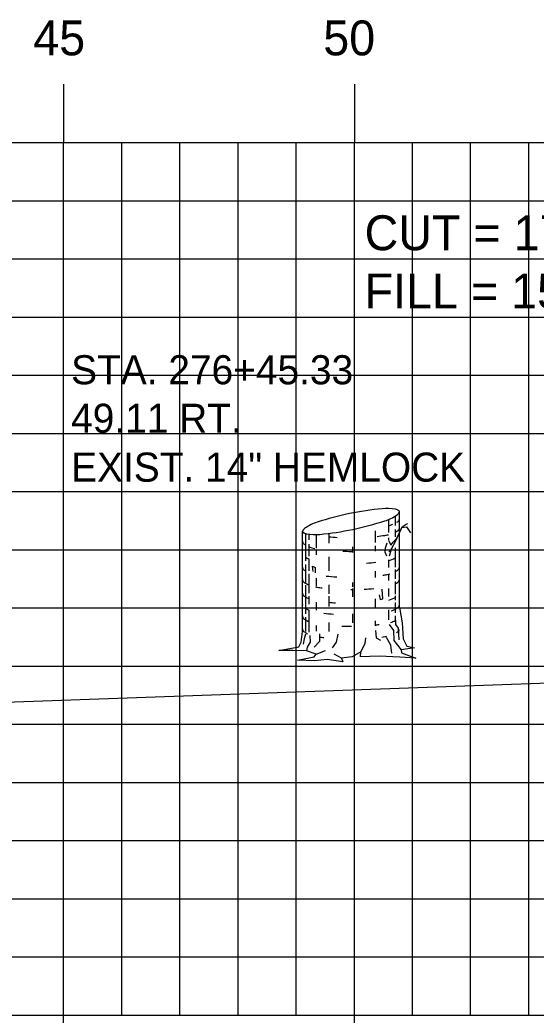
# Model space of a CAD drawing. Extents: x 854008 to 854178, y 366268 to 366378.
# Drawn here: x 854135.35 to 854144.23, y 366277.24 to 366294.35 of the extents above; entities that cross this region are included whole.
import ezdxf

# ---------------------------------------------------------------- set-up
doc = ezdxf.new("R2010")
doc.units = 0
for name, color, linetype in [('ANNOTATION', 7, 'Continuous'), ('D_Text_Monospaced', 7, 'Continuous'), ('H_V ANNOTATION', 7, 'Continuous'), ('MAJOR', 7, 'Continuous'), ('MINOR', 7, 'Continuous'), ('S_Roadway_Centerline', 7, 'Continuous'), ('S_Trees_Conifer_Pay', 7, 'Continuous')]:
    doc.layers.add(name, color=color, linetype=linetype)

msp = doc.modelspace()

# ---------------------------------------------------------------- linework, layer by layer
at = {"layer": 'MAJOR'}
for p, q in [((854136.103, 366293.238), (854136.103, 366292.236)), ((854141.103, 366293.238), (854141.103, 366292.236)), ((854021.103, 366292.236), (854161.103, 366292.236)), ((854021.103, 366292.236), (854161.103, 366292.236)), ((854136.103, 366277.236), (854136.103, 366292.236)), ((854141.103, 366277.236), (854141.103, 366292.236)), ((854021.103, 366287.236), (854161.103, 366287.236)), ((854021.103, 366282.236), (854161.103, 366282.236)), ((854021.103, 366277.236), (854161.103, 366277.236)), ((854021.103, 366277.236), (854161.103, 366277.236)), ((854136.103, 366276.234), (854136.103, 366277.236)), ((854141.103, 366276.234), (854141.103, 366277.236))]:
    msp.add_line(p, q, dxfattribs=at)
at = {"layer": 'MINOR'}
for p, q in [((854137.103, 366277.236), (854137.103, 366292.236)), ((854138.103, 366277.236), (854138.103, 366292.236)), ((854139.103, 366277.236), (854139.103, 366292.236)), ((854140.103, 366277.236), (854140.103, 366292.236)), ((854142.103, 366277.236), (854142.103, 366292.236)), ((854143.103, 366277.236), (854143.103, 366292.236)), ((854144.103, 366277.236), (854144.103, 366292.236)), ((854021.103, 366291.236), (854161.103, 366291.236)), ((854021.103, 366290.236), (854161.103, 366290.236)), ((854021.103, 366289.236), (854161.103, 366289.236)), ((854021.103, 366288.236), (854161.103, 366288.236)), ((854021.103, 366286.236), (854161.103, 366286.236)), ((854021.103, 366285.236), (854161.103, 366285.236)), ((854021.103, 366284.236), (854161.103, 366284.236)), ((854021.103, 366283.236), (854161.103, 366283.236)), ((854021.103, 366281.236), (854161.103, 366281.236)), ((854021.103, 366280.236), (854161.103, 366280.236)), ((854021.103, 366279.236), (854161.103, 366279.236)), ((854021.103, 366278.236), (854161.103, 366278.236))]:
    msp.add_line(p, q, dxfattribs=at)
at = {"layer": 'S_Roadway_Centerline'}
msp.add_lwpolyline([(854119.24, 366283.569), (854127.488, 366282.734), (854134.932, 366282.61), (854144.452, 366282.95), (854151.493, 366282.391), (854151.803, 366282.4), (854152.599, 366282.401)], dxfattribs=at)
at = {"layer": 'S_Trees_Conifer_Pay'}
for p, q in [((854141.688, 366285.756), (854141.688, 366285.533)), ((854141.806, 366285.817), (854141.806, 366285.654)), ((854141.877, 366284.242), (854141.877, 366285.889)), ((854141.46, 366285.56), (854141.46, 366285.36)), ((854141.806, 366285.587), (854141.806, 366285.459)), ((854140.213, 366283.832), (854140.213, 366285.554)), ((854140.26, 366285.516), (854140.26, 366285.045)), ((854140.319, 366285.505), (854140.319, 366285.407)), ((854140.444, 366285.497), (854140.444, 366285.265)), ((854140.664, 366285.518), (854140.664, 366285.35)), ((854141.688, 366285.444), (854141.688, 366285.397)), ((854140.319, 366285.333), (854140.319, 366285.129)), ((854140.444, 366285.224), (854140.444, 366285.15)), ((854141.069, 366285.286), (854141.069, 366285.191)), ((854141.46, 366285.303), (854141.46, 366285.214)), ((854141.745, 366285.261), (854141.694, 366285.201)), ((854141.806, 366285.272), (854141.806, 366284.936)), ((854140.319, 366285.072), (854140.319, 366284.872)), ((854140.664, 366285.113), (854140.664, 366284.876)), ((854141.688, 366285.062), (854141.688, 366284.93)), ((854140.26, 366284.981), (854140.26, 366284.673)), ((854141.806, 366284.899), (854141.806, 366284.736)), ((854140.319, 366284.825), (854140.319, 366284.489)), ((854140.444, 366284.747), (854140.444, 366284.608)), ((854141.46, 366284.866), (854141.46, 366284.761)), ((854141.688, 366284.819), (854141.688, 366284.709)), ((854140.26, 366284.625), (854140.26, 366284.133)), ((854140.664, 366284.631), (854140.664, 366284.479)), ((854141.069, 366284.673), (854141.069, 366284.598)), ((854141.069, 366284.573), (854141.069, 366284.425)), ((854141.688, 366284.573), (854141.688, 366284.432)), ((854141.806, 366284.689), (854141.806, 366284.472)), ((854140.319, 366284.436), (854140.319, 366284.3)), ((854140.664, 366284.436), (854140.664, 366284.262)), ((854141.46, 366284.394), (854141.46, 366284.248)), ((854141.806, 366284.442), (854141.806, 366284.367)), ((854140.319, 366284.201), (854140.319, 366283.822)), ((854140.444, 366284.337), (854140.444, 366284.195)), ((854141.688, 366284.205), (854141.688, 366284.032)), ((854141.806, 366284.327), (854141.806, 366284.154)), ((854140.26, 366284.079), (854140.26, 366283.832)), ((854141.069, 366284.133), (854141.069, 366283.98)), ((854140.444, 366283.933), (854140.444, 366283.839)), ((854140.664, 366283.985), (854140.664, 366283.832)), ((854141.46, 366284.016), (854141.46, 366283.927)), ((854140.444, 366283.439), (854140.607, 366283.503)), ((854140.881, 366283.375), (854140.755, 366283.439))]:
    msp.add_line(p, q, dxfattribs=at)
for points in [[(854141.694, 366285.387), (854141.731, 366285.313), (854141.778, 366285.37), (854141.836, 366285.438), (854141.928, 366285.632), (854141.993, 366285.679), (854142.024, 366285.686)], [(854141.709, 366285.134), (854141.745, 366285.261), (854141.809, 366285.377), (854141.84, 366285.444), (854141.909, 366285.591)], [(854141.923, 366285.62), (854141.999, 366285.628), (854142.071, 366285.529)], [(854141.661, 366285.35), (854141.63, 366285.265), (854141.626, 366285.198), (854141.657, 366285.134)], [(854140.392, 366284.86), (854140.386, 366284.955), (854140.43, 366284.932), (854140.43, 366284.837)], [(854141.531, 366284.461), (854141.544, 366284.384), (854141.591, 366284.394), (854141.579, 366284.561)], [(854141.877, 366284.242), (854141.928, 366283.98), (854141.945, 366283.707), (854142.003, 366283.581), (854142.138, 366283.551), (854141.908, 366283.513), (854141.908, 366283.513), (854141.914, 366283.466), (854142.161, 366283.371), (854141.887, 366283.388), (854141.531, 366283.408), (854141.21, 366283.398), (854141.216, 366283.48), (854141.068, 366283.398), (854140.881, 366283.375), (854140.905, 366283.307), (854140.638, 366283.35), (854140.417, 366283.324), (854140.125, 366283.341), (854140.413, 366283.398), (854140.444, 366283.439), (854140.281, 366283.497), (854140.045, 366283.507), (854139.804, 366283.507), (854140.146, 366283.565), (854140.187, 366283.645), (854140.213, 366283.832)], [(854141.803, 366284.1), (854141.809, 366283.954), (854141.856, 366283.886), (854141.867, 366283.686)], [(854141.467, 366283.849), (854141.478, 366283.723), (854141.552, 366283.68)], [(854141.704, 366283.954), (854141.778, 366283.849), (854141.783, 366283.676), (854141.908, 366283.513)], [(854140.261, 366283.785), (854140.24, 366283.707), (854140.22, 366283.612)], [(854140.339, 366283.764), (854140.345, 366283.649), (854140.292, 366283.56), (854140.281, 366283.497)], [(854140.502, 366283.791), (854140.502, 366283.659), (854140.413, 366283.56)], [(854140.728, 366283.551), (854140.796, 366283.645), (854140.823, 366283.785)], [(854141.216, 366283.48), (854141.291, 366283.622), (854141.3, 366283.723)], [(854141.745, 366283.46), (854141.731, 366283.598), (854141.657, 366283.727)]]:
    msp.add_lwpolyline(points, dxfattribs=at)
for centre, radius, start, end in [((854142.069, 366280.786), 5.179, 95.3794, 101.7194), ((854141.659, 366285.144), 0.802, 79.2194, 95.3794), ((854141.762, 366285.685), 0.251, 71.0501, 79.2194), ((854141.817, 366285.845), 0.0817, 56.7194, 71.0501), ((854141.832, 366285.869), 0.0527, 46.923, 56.7194), ((854141.847, 366285.885), 0.0314, 34.2194, 46.923), ((854141.851, 366285.888), 0.0264, 23.4074, 34.2194), ((854142.069, 366280.786), 5.179, 101.7194, 108.0594), ((854140.022, 366290.657), 5.179, 281.7194, 288.0594), ((854141.378, 366286.495), 0.802, 288.0594, 304.2194), ((854141.688, 366286.039), 0.251, 304.2194, 312.3887), ((854141.746, 366285.858), 0.172, 300, 311.2506), ((854141.802, 366285.915), 0.0817, 312.3887, 326.7194), ((854141.818, 366285.775), 0.0624, 311.2506, 330), ((854141.826, 366285.899), 0.0527, 326.7194, 336.5158), ((854141.834, 366285.766), 0.0441, 330, 343.9485), ((854141.855, 366285.889), 0.0226, 11.7194, 23.4074), ((854141.846, 366285.89), 0.0314, 336.5158, 349.2194), ((854141.844, 366285.763), 0.0334, 343.9485, 354.2151), ((854141.855, 366285.889), 0.0226, 0.0315, 11.7194), ((854141.851, 366285.889), 0.0264, 349.2194, 0.0315), ((854140.24, 366285.554), 0.0264, 169.2194, 180.0315), ((854140.245, 366285.553), 0.0314, 156.5158, 169.2194), ((854140.264, 366285.544), 0.0527, 146.7194, 156.5158), ((854140.288, 366285.528), 0.0817, 132.3887, 146.7194), ((854140.402, 366285.403), 0.251, 124.2194, 132.3887), ((854140.712, 366284.948), 0.802, 108.0594, 124.2194), ((854140.022, 366290.657), 5.179, 275.3794, 281.7194), ((854141.546, 366286.203), 0.571, 284.4317, 292.4132), ((854141.746, 366285.703), 0.172, 300, 311.2506), ((854141.818, 366285.621), 0.0624, 311.2506, 330), ((854141.834, 366285.611), 0.0441, 330, 343.9485), ((854141.844, 366285.608), 0.0334, 343.9485, 354.2151), ((854140.236, 366285.554), 0.0226, 180.0315, 191.7194), ((854140.236, 366285.554), 0.0226, 191.7194, 203.4074), ((854140.239, 366285.555), 0.0264, 203.4074, 214.2194), ((854140.244, 366285.558), 0.0314, 214.2194, 226.923), ((854140.258, 366285.573), 0.0527, 226.923, 236.7194), ((854140.274, 366285.598), 0.0817, 236.7194, 251.0501), ((854140.329, 366285.757), 0.251, 251.0501, 259.2194), ((854140.432, 366286.299), 0.802, 259.2194, 275.3794), ((854141.045, 366289.566), 4.124, 264.6955, 266.7331), ((854141.045, 366289.566), 4.124, 276.238, 278.1032), ((854141.546, 366286.048), 0.571, 278.1032, 284.3667), ((854141.546, 366286.048), 0.571, 297.0237, 300), ((854140.245, 366285.376), 0.0334, 163.9485, 180), ((854140.245, 366285.376), 0.0334, 180, 196.0515), ((854140.256, 366285.379), 0.0441, 196.0515, 210), ((854140.271, 366285.388), 0.0624, 210, 228.7494), ((854140.344, 366285.47), 0.172, 228.7494, 240), ((854140.543, 366285.815), 0.571, 240, 240.3367), ((854140.543, 366285.815), 0.571, 246.8597, 257.9846), ((854141.044, 366289.333), 4.124, 275.7849, 277.0558), ((854140.544, 366285.604), 0.571, 240, 247.0587), ((854141.044, 366289.333), 4.124, 268.0751, 270), ((854141.044, 366289.333), 4.124, 270, 270.3581), ((854141.546, 366285.604), 0.571, 284.4493, 297.0429), ((854141.844, 366285.164), 0.0334, 343.9485, 354.2151), ((854140.245, 366284.929), 0.0334, 163.9485, 180), ((854140.245, 366284.929), 0.0334, 180, 196.0515), ((854140.256, 366284.932), 0.0441, 196.0515, 210), ((854140.271, 366284.941), 0.0624, 210, 228.7494), ((854140.344, 366285.023), 0.172, 228.7494, 240), ((854140.543, 366285.369), 0.571, 240, 240.3367), ((854141.045, 366289.122), 4.124, 273.7052, 275.9504), ((854141.545, 366285.369), 0.571, 297.1896, 300), ((854141.744, 366285.023), 0.172, 300, 311.2506), ((854141.816, 366284.941), 0.0624, 311.2506, 330), ((854141.832, 366284.932), 0.0441, 330, 343.9485), ((854141.843, 366284.929), 0.0334, 343.9485, 354.2151), ((854140.245, 366284.719), 0.0334, 163.9485, 180), ((854140.245, 366284.719), 0.0334, 180, 196.0515), ((854140.256, 366284.722), 0.0441, 196.0515, 210), ((854141.044, 366288.886), 4.124, 264.081, 266.6676), ((854141.044, 366288.886), 4.124, 277.6125, 278.1032), ((854141.545, 366285.369), 0.571, 278.1032, 286.9296), ((854141.832, 366284.722), 0.0441, 330, 343.9485), ((854141.843, 366284.719), 0.0334, 343.9485, 354.2151), ((854140.271, 366284.731), 0.0624, 210, 228.7494), ((854140.344, 366284.813), 0.172, 228.7494, 240), ((854140.543, 366285.159), 0.571, 240, 246.8597), ((854140.543, 366285.159), 0.571, 259.2707, 261.8968), ((854141.044, 366288.676), 4.124, 261.8968, 263.1474), ((854141.044, 366288.676), 4.124, 270, 270.3581), ((854141.044, 366288.676), 4.124, 273.1493, 275.4569), ((854141.545, 366285.159), 0.571, 297.1896, 300), ((854141.744, 366284.813), 0.172, 300, 311.2506), ((854141.816, 366284.731), 0.0624, 311.2506, 330), ((854140.245, 366284.482), 0.0334, 163.9485, 180), ((854140.245, 366284.482), 0.0334, 180, 196.0515), ((854140.256, 366284.485), 0.0441, 196.0515, 210), ((854140.271, 366284.494), 0.0624, 210, 228.7494), ((854140.344, 366284.577), 0.172, 228.7494, 240), ((854140.543, 366284.922), 0.571, 240, 246.8597), ((854141.545, 366284.922), 0.571, 285.3983, 297.1896), ((854140.245, 366284.284), 0.0334, 163.9485, 180), ((854140.532, 366284.73), 0.571, 241.2369, 248.0268), ((854141.044, 366288.439), 4.124, 264.716, 266.3193), ((854141.545, 366284.724), 0.571, 289.2907, 300), ((854141.744, 366284.379), 0.172, 300, 311.2506), ((854141.816, 366284.296), 0.0624, 311.2506, 330), ((854141.832, 366284.287), 0.0441, 330, 343.9485), ((854141.843, 366284.284), 0.0334, 343.9485, 354.2151), ((854140.245, 366284.089), 0.0334, 163.9485, 180), ((854140.245, 366284.089), 0.0334, 180, 196.0515), ((854140.256, 366284.092), 0.0441, 196.0515, 210), ((854140.271, 366284.101), 0.0624, 210, 228.7494), ((854140.344, 366284.183), 0.172, 228.7494, 240), ((854140.543, 366284.528), 0.571, 240, 246.8597), ((854141.044, 366288.242), 4.124, 263.4991, 265.8397), ((854141.545, 366284.528), 0.571, 288.5067, 297.2721), ((854140.245, 366283.868), 0.0334, 163.9485, 180), ((854140.245, 366283.868), 0.0334, 180, 196.0515), ((854140.256, 366283.871), 0.0441, 196.0515, 210), ((854140.271, 366283.88), 0.0624, 210, 228.7494), ((854141.044, 366288.046), 4.124, 267.8117, 270), ((854141.044, 366288.046), 4.124, 270, 270.1328), ((854141.044, 366288.046), 4.124, 275.7849, 276.7896), ((854141.816, 366283.88), 0.0624, 311.2506, 330), ((854141.832, 366283.871), 0.0441, 330, 343.9485), ((854141.843, 366283.868), 0.0334, 343.9485, 354.2151), ((854140.344, 366283.963), 0.172, 228.7494, 240), ((854140.543, 366284.308), 0.571, 240, 244.5314), ((854141.044, 366287.826), 4.124, 262.4438, 263.512), ((854141.044, 366287.826), 4.124, 277.3684, 278.1032), ((854141.545, 366284.308), 0.571, 278.1032, 281.637), ((854141.744, 366283.963), 0.172, 300, 311.2506)]:
    msp.add_arc(centre, radius, start, end, dxfattribs=at)

# ---------------------------------------------------------------- texts
at = {"layer": 'ANNOTATION'}
for s, p in [('CUT = 177.7 C.Y.', (854141.279, 366290.386)), ('FILL = 15.8 C.Y.', (854141.279, 366289.384))]:
    msp.add_text(s, height=0.6, dxfattribs=at).set_placement(p)
at = {"layer": 'D_Text_Monospaced'}
for s, height, p in [('STA. 276+45.33', 0.49998, (854136.232, 366288.081)), ('49.11 RT.', 0.5, (854136.232, 366287.247)), ('EXIST. 14" HEMLOCK', 0.49998, (854136.232, 366286.407))]:
    msp.add_text(s, height=height, dxfattribs=at).set_placement(p)
at = {"layer": 'H_V ANNOTATION'}
for s, p in [('45', (854135.581, 366293.736)), ('50', (854140.568, 366293.736))]:
    msp.add_text(s, height=0.6, dxfattribs=at).set_placement(p)

doc.saveas('drawing.dxf')
